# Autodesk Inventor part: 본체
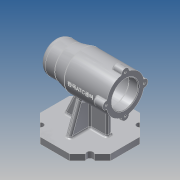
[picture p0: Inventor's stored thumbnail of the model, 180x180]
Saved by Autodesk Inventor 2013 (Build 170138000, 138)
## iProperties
Created: 2019-12
Part Number: 본체
Material: 알루미늄 6061
Document SubType Name: Modeling
Designer: Administrator
Density: 2.71 g/cm^3
Mass: 728.494 g
Surface Area: 714.679 cm^2
Volume: 268.817 cm^3
Author: Administrator
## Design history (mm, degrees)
sketch "스케치1"
  geometry: L1 (-56, 0)-(56, 0); L2 (-56, 0)-(-56, 25); L3 (-56, 25)-(-31, 25); L4 (-31, 25)-(-11, 30); L5 (-11, 30)-(56, 30); L6 (56, 30)-(56, 0); 2 further points
  constraints: 12 end point, 2 parallel, 2 perpendicular, 1 coincident, 1 horizontal, 1 midpoint
  dimensions: "d0" = 112 distance of L1.start L1.end; "d2" = 25 distance of L2.end L3.end; "d3" = 45 distance from line of L2 L4.end; "d4" = 50 diameter of L3 L1; "d5" = 60 diameter of L5 L1
revolve "회전1" sketch "스케치1" stored, may be unused: angle "d6" = 90 deg
node "작업 평면1"
sketch "스케치2"
  geometry: L1 (23.196, 56)-(56, 23.196); L2 (56, 23.196)-(56, -23.196); L3 (56, -23.196)-(23.196, -56); L4 (23.196, -56)-(-23.196, -56); L5 (-23.196, -56)-(-56, -23.196); L6 (-56, -23.196)-(-56, 23.196); L7 (-56, 23.196)-(-23.196, 56); L8 (-23.196, 56)-(23.196, 56); 3 further points
  constraints: 16 end point, 1 coincident, 1 midpoint, 1 vertical alignment, 17 other
  dimensions: "d8" = 56 distance from line of L2 point (0, 0)
extrude "돌출1" join sketch "스케치2" distance "d9" = 10; taper "d10" = 0 deg
sketch "스케치3"
  geometry: L1 (56, 25)-(56, -25) reference; L2 (56, -25)-(31, -25) reference; L3 (31, -25)-(11, -30) reference; L4 (11, -30)-(-56, -30) reference; L5 (-56, -30)-(-56, 30) reference; L6 (-56, 30)-(11, 30) reference; L7 (11, 30)-(31, 25) reference; L8 (31, 25)-(56, 25) reference; L9 (56, -70)-(56, -80) reference; L10 (56, -80)-(-56, -80) reference; L11 (-56, -80)-(-56, -70) reference; L12 (-56, -70)-(56, -70) reference; L13 (38, -70)-(5.358, 0); L14 (5.358, 0)-(-31, 0); L15 (-31, 0)-(-31, -70); L16 (-31, -70)-(38, -70); 1 further point
  constraints: 8 end point, 3 point on line, 1 collinear, 1 parallel, 1 perpendicular
  dimensions: "d11" = 115 deg angle of L13 L12; "d12" = 25 distance between parallel lines of L11 L15; "d13" = 18 distance from line of L9 L13.start
extrude "돌출2" join sketch "스케치3" stored distance "d14" = 8; taper "d15" = 0 deg
sketch "스케치4"
  geometry: L1 (-56, -80)-(-56, -70) reference; L2 (-56, -70)-(-4, -70) reference; L3 (-4, -70)-(-4, -29.732) reference; L4 (4, -29.732)-(4, -70) reference; L5 (4, -70)-(56, -70) reference; L6 (56, -70)-(56, -80) reference; L7 (56, -80)-(-56, -80) reference; L8 (-36, -70)-(-18.979, -23.234); A1 r 30 centre (0, 0) between (4, -29.732) and (-4, -29.732) reference; 1 further point
  constraints: 2 end point, 1 point on circle, 1 point on line
  dimensions: "d16" = 20 distance from line of L8.start L1; "d17" = 110 deg angle of L8 L2
feature "리브1" sketch "스케치4" dims "d18" = 1, "d19" = 8, "d20" = 0, "d21" = 0, "d22" = 1, "d23" = 1
sketch "스케치5"
  geometry: C1 r 6 at (-30, 0); 1 further point
  constraints: 2 horizontal alignment, 1 centre point, 1 other
  dimensions: "d24" = 12 diameter of C1
extrude "돌출3" join sketch "스케치5" distance "d25" = 16; taper "d26" = 0 deg
sketch "스케치6"
  geometry: A1 r 6 centre (0, 0) between (0.6, 5.97) and (0.6, -5.97) reference
hole "구멍1" sketch "스케치6" at (0, 0) diameter "d27" = 3.242; stored, may be unused: countersink angle "d31" = 90 deg, drill point angle "d33" = 118 deg; dims "d28" = 8, "d29" = 4, "d30" = 2, "d32" = 11
sketch "스케치7"
  geometry: L1 (23.196, -56)-(56, -23.196) reference; L2 (56, 23.196)-(23.196, 56) reference; L3 (-23.196, 56)-(-56, 23.196) reference; L4 (-56, -23.196)-(-23.196, -56) reference; C1 r 5 at (-39.598, 39.598); C2 r 5 at (-39.598, -39.598); C3 r 5 at (39.598, 39.598); C4 r 5 at (39.598, -39.598); 1 further point
  constraints: 4 centre point, 4 midpoint
  dimensions: "d37" = 10 diameter of C1; "d38" = 10 diameter of C2; "d39" = 10 diameter of C3; "d40" = 10 diameter of C4
extrude "돌출4" cut sketch "스케치7" stored distance "d41" = 16; taper "d42" = 0 deg
sketch "스케치8"
  geometry: L1 (56, 25)-(56, -25) reference; L2 (56, -25)-(31, -25) reference; L3 (31, -25)-(18.476, -28.131) reference; L4 (18.476, -28.131)-(38, -70) reference; L5 (38, -70)-(56, -70) reference; L6 (56, -70)-(56, -80) reference; L7 (56, -80)-(-56, -80) reference; L8 (-56, -80)-(-56, -70) reference; L9 (-56, -70)-(-31, -70) reference; L10 (-31, -70)-(-31, -30) reference; L11 (-31, -30)-(-40, -30) reference; L12 (-40, -30)-(-40, -36) reference; L13 (-40, -36)-(-56, -36) reference; L14 (-56, -36)-(-56, -31.621) reference; L15 (-56, -31.621)-(-45, -31.621) reference; L16 (-45, -31.621)-(-44.026, -30) reference; L17 (-44.026, -30)-(-45, -28.379) reference; L18 (-45, -28.379)-(-56, -28.379) reference; L19 (-56, -28.379)-(-56, 28.379) reference; L20 (-56, 28.379)-(-45, 28.379) reference; L21 (-45, 28.379)-(-44.026, 30) reference; L22 (-44.026, 30)-(-45, 31.621) reference; L23 (-45, 31.621)-(-56, 31.621) reference; L24 (-56, 31.621)-(-56, 36) reference; L25 (-56, 36)-(-40, 36) reference; L26 (-40, 36)-(-40, 30) reference; L27 (-40, 30)-(11, 30) reference; L28 (11, 30)-(31, 25) reference; L29 (31, 25)-(56, 25) reference; L30 (50, 0)-(-56, 0); L31 (50, 0)-(50, 10.5); L32 (50, 10.5)-(47, 10.5); L33 (47, 10.5)-(47, 16); L34 (47, 16)-(43, 16); L35 (43, 16)-(43, 17.5); L36 (43, 17.5)-(25, 17.5); L37 (25, 17.5)-(25, 21); L38 (25, 21)-(13, 21); L39 (13, 21)-(13, 24); L40 (13, 24)-(-41, 24); L41 (-41, 24)-(-41, 21); L42 (-41, 21)-(-56, 21); L43 (-56, 21)-(-56, 0); 1 further point
  constraints: 28 end point, 12 parallel, 2 perpendicular, 2 point on line, 1 collinear, 1 midpoint
  dimensions: "d43" = 15 distance between parallel lines of L43 L41; "d45" = 54 distance between parallel lines of L41 L39; "d46" = 3 distance of L31.end L32.end; "d47" = 12 distance of L37.end L38.end; "d48" = 18 distance of L35.end L36.end; "d49" = 4 distance of L33.end L34.end; "d50" = 42 diameter of L42 L30; "d51" = 48 diameter of L40 L30; "d52" = 42 diameter of L38 L30; "d53" = 21 diameter of L32 L30; "d54" = 32 diameter of L34 L30; "d55" = 35 diameter of L36 L30
revolve "회전2" sketch "스케치8" stored, may be unused: angle "d56" = 90 deg
fillet "모깎기1" dims "d57" = 0.3
fillet "모깎기2" dims "d58" = 3
chamfer "모따기1" distance "d59" = 1; stored, may be unused: second distance "d60" = 2, angle "d61" = 45 deg
fillet "모깎기3" dims "d62" = 3
fillet "모깎기4" dims "d63" = 1
fillet "모깎기5" dims "d64" = 10
fillet "모깎기6" dims "d65" = 3
node "작업 평면2"
sketch "스케치9"
  geometry: L1 (-10.631, -29.732)-(-10.631, -29.732) reference; L2 (-10.631, -29.732)-(-4, -29.732) reference; L3 (-4, -29.732)-(-4, -23.234) reference; L4 (-4, -23.234)-(4, -23.234) reference; L5 (4, -23.234)-(4, -29.732) reference; L6 (4, -29.732)-(31, -29.732) reference; L7 (31, -29.732)-(31, -29.732) reference; L8 (31, -29.732)-(4, -29.732) reference; L9 (4, -29.732)-(4, -23.234) reference; L10 (4, -23.234)-(-4, -23.234) reference; L11 (-4, -23.234)-(-4, -29.732) reference; L12 (-4, -29.732)-(-10.631, -29.732) reference; L13 (56, -6.771)-(43, -6.771) reference; L14 (56, -29.226)-(56, -6.771) reference; L15 (43, -29.226)-(56, -29.226) reference; L16 (39, -29.871)-(39, -29.871) reference; L17 (56, -29.226)-(43, -29.226) reference; L18 (56, -6.771)-(56, -29.226) reference; L19 (43, -6.771)-(56, -6.771) reference; L20 (39, 2.779)-(39, -2.779) reference; L21 (56, 6.771)-(43, 6.771) reference; L22 (56, 29.226)-(56, 6.771) reference; L23 (43, 29.226)-(56, 29.226) reference; L24 (39, 29.871)-(39, 29.871) reference; L25 (56, 29.226)-(43, 29.226) reference; L26 (56, 6.771)-(56, 29.226) reference; L27 (43, 6.771)-(56, 6.771) reference; L28 (39, -2.779)-(39, 2.779) reference; 2 further points
  constraints: 1 horizontal alignment, 9 other
  dimensions: "d67" = 41 distance from line of L22 point (15, 0)
feature "엠보싱1" sketch "스케치9" dims "d0" = 112, "d2" = 25, "d3" = 45, "d4" = 50, "d5" = 60, "d68" = 0.5, "d69" = 0
fillet "모깎기7" dims "d70" = 3
fillet "모깎기8" dims "d71" = 3
fillet "모깎기9" dims "d72" = 3
node "솔리드1"
mirror "대칭1"
pattern_circular "원형 패턴1" dims angle "d35" = 360 deg
node "투영된 루프1"
node "절단 모서리 투영1"
node "절단 모서리 투영2"
node "절단 모서리 투영3"
other parameters: "d66" = -98.5
